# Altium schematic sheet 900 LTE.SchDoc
size Letter; Organization: Toradex Solutions Inc.; Address1: 6415 Northwest Drive; Address2: Mississauga, ON, L4V 1X1; Address3: Canada
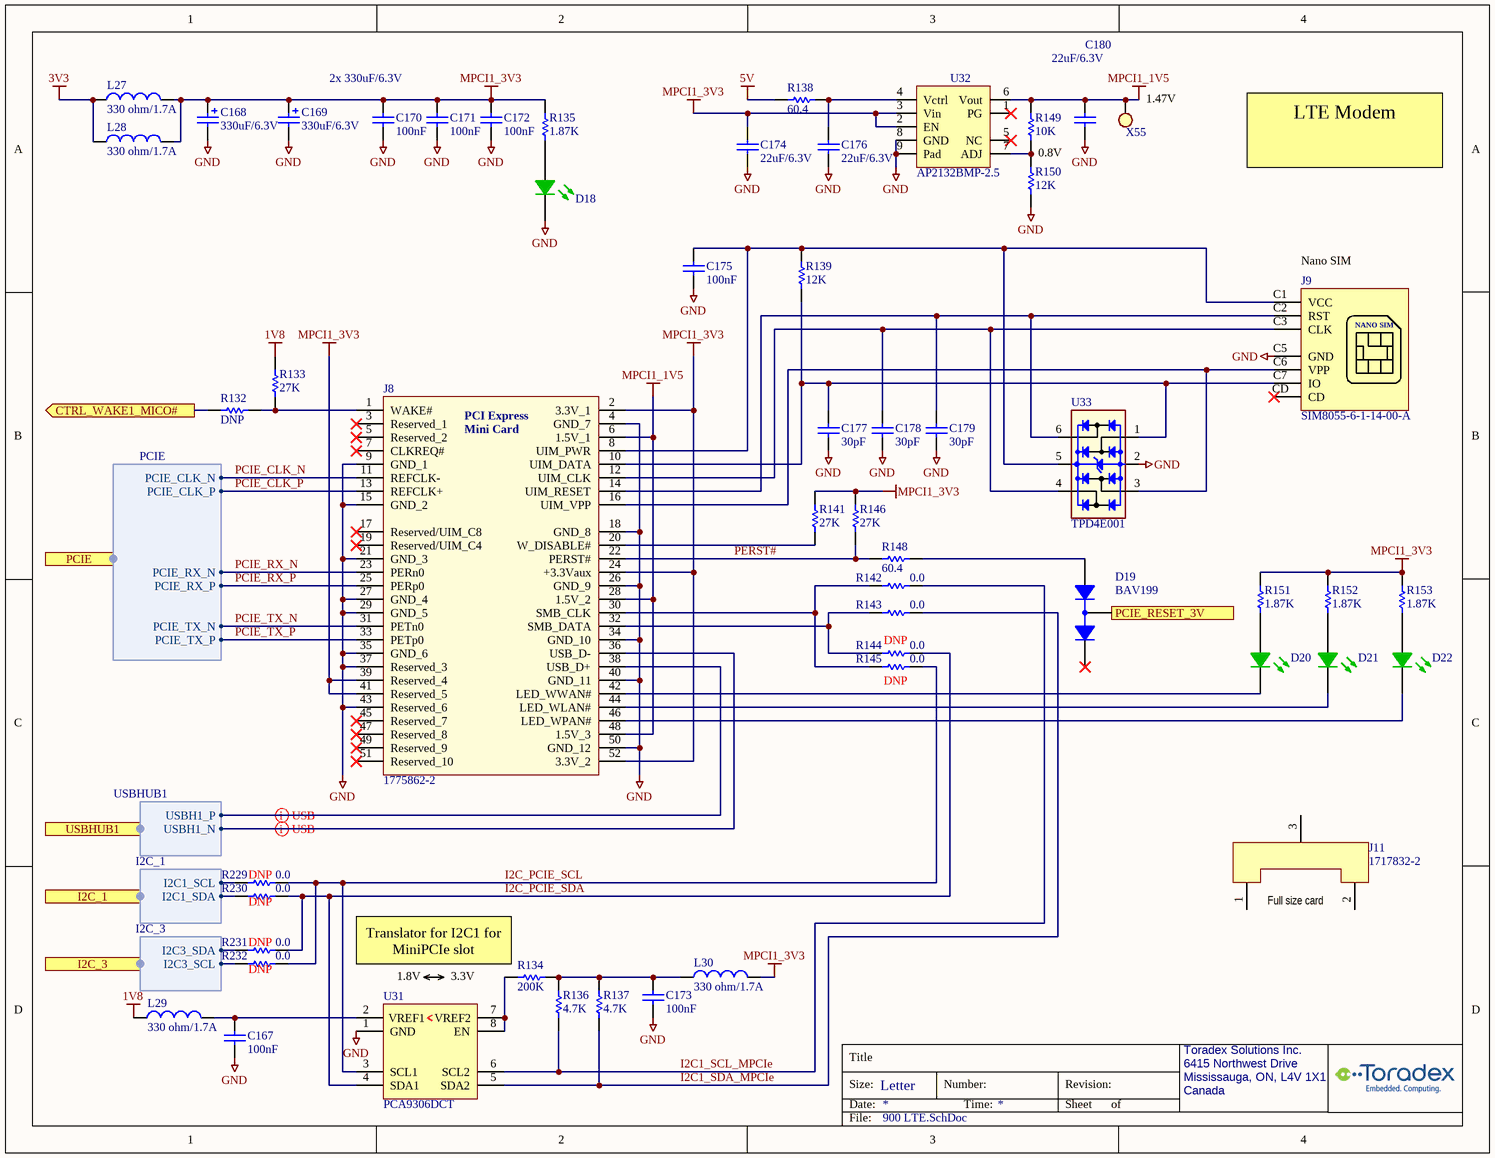
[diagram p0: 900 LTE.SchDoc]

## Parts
C167  100nF  [C0402_CAPC1005L]
C168  330uF/6.3V  [CAN-SMD-D630]
C169  330uF/6.3V  [CAN-SMD-D630]
C170  100nF  [C0402_CAPC1005L]
C171  100nF  [C0402_CAPC1005L]
C172  100nF  [C0402_CAPC1005L]
C173  100nF  [C0402_CAPC1005L]
C174  22uF/6.3V  [C0402_CAPC1005L]
C175  100nF  [C0402_CAPC1005L]
C176  22uF/6.3V  [C0402_CAPC1005L]
C177  value 30pF  [C/0603]  (hidden comment: 0958-Cap-0603-30pF/50V)
C178  value 30pF  [C/0603]  (hidden comment: 0958-Cap-0603-30pF/50V)
C179  value 30pF  [C/0603]  (hidden comment: 0958-Cap-0603-30pF/50V)
C180  22uF/6.3V  [C0402_CAPC1005L]
D18  Status  [LED-SMT-0603_APT1608CGCK]  (value not drawn)
D19  BAV199  [SOT23_M]
D20  Status  [LED-SMT-0603_APT1608CGCK]  (value not drawn)
D21  Status  [LED-SMT-0603_APT1608CGCK]  (value not drawn)
D22  Status  [LED-SMT-0603_APT1608CGCK]  (value not drawn)
J8  1775862-2  [17758622_FULL_SIZE]
J9  SIM8055-6-1-14-00-A  [SIM8055611400A]
J11  1717832-2  [MINI_PCIE_52PIN_CARD_LATCH_ALT]
L27  value 330 ohm/1.7A  [INDC1608x095]  (hidden comment: 0405-Fer-0603-330ohm/1.7A)
L28  value 330 ohm/1.7A  [INDC1608x095]  (hidden comment: 0405-Fer-0603-330ohm/1.7A)
L29  value 330 ohm/1.7A  [INDC1608x095]  (hidden comment: 0405-Fer-0603-330ohm/1.7A)
L30  value 330 ohm/1.7A  [INDC1608x095]  (hidden comment: 0405-Fer-0603-330ohm/1.7A)
R132  value DNP  [R/0603]  (hidden comment: 0000-Res-0603-DNP)
R133  value 27K  [R0402_RESC1005L]  (hidden comment: 1538-Res-0402-27k)
R134  value 200K  [R/0603]  (hidden comment: 1367-Res-0603-200K)
R135  value 1.87K  [R0402_RESC1005L]  (hidden comment: 1536-Res-0402-1.87K)
R136  value 4.7K  [R0402_RESC1005L]  (hidden comment: 2233-Res-0402-4.7K)
R137  value 4.7K  [R0402_RESC1005L]  (hidden comment: 2233-Res-0402-4.7K)
R138  value 60.4  [R/0603]  (hidden comment: 2199-Res-0603-60.4)
R139  value 12K  [R0402_RESC1005L]  (hidden comment: 1537-Res-0402-12K)
R141  value 27K  [R0402_RESC1005L]  (hidden comment: 1538-Res-0402-27k)
R142  value 0.0  [R/0603]  (hidden comment: 0195-Res-0603-0.0ohm)
R143  value 0.0  [R/0603]  (hidden comment: 0195-Res-0603-0.0ohm)
R144  value 0.0  [R/0603]  (hidden comment: 0195-Res-0603-0.0ohm)  (no BOM)
R145  value 0.0  [R/0603]  (hidden comment: 0195-Res-0603-0.0ohm)  (no BOM)
R146  value 27K  [R0402_RESC1005L]  (hidden comment: 1538-Res-0402-27k)
R148  value 60.4  [R/0603]  (hidden comment: 2199-Res-0603-60.4)
R149  value 10K  [R0402_RESC1005L]  (hidden comment: 1572-Res-0402-10K)
R150  value 12K  [R0402_RESC1005L]  (hidden comment: 1537-Res-0402-12K)
R151  value 1.87K  [R0402_RESC1005L]  (hidden comment: 1536-Res-0402-1.87K)
R152  value 1.87K  [R0402_RESC1005L]  (hidden comment: 1536-Res-0402-1.87K)
R153  value 1.87K  [R0402_RESC1005L]  (hidden comment: 1536-Res-0402-1.87K)
R229  value 0.0  [R/0603]  (hidden comment: 0195-Res-0603-0.0ohm)  (no BOM)
R230  value 0.0  [R/0603]  (hidden comment: 0195-Res-0603-0.0ohm)  (no BOM)
R231  value 0.0  [R/0603]  (hidden comment: 0195-Res-0603-0.0ohm)  (no BOM)
R232  value 0.0  [R/0603]  (hidden comment: 0195-Res-0603-0.0ohm)  (no BOM)
U31  PCA9306DCT  [TSSO3x5-G8/X.35]
U32  AP2132BMP-2.5  [SOP-9 TP_ALT]
U33  TPD4E001  [SOT23-6]
X55  000-TestPoint2  [TestPoint_3]  (value not drawn)

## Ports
CTRL_WAKE1_MICO# (out), I2C_1 (harness I2C_1), I2C_3 (harness I2C_3), PCIE (harness PCIe), PCIE_RESET_3V (in), USBHUB1 (harness USBHUB1)

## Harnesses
PCIE: PCIE_CLK_N, PCIE_CLK_P, PCIE_RX_N, PCIE_RX_P, PCIE_TX_N, PCIE_TX_P
USBHUB1: USBH1_N, USBH1_P
I2C_1: I2C1_SDA, I2C1_SCL
I2C_3: I2C3_SDA, I2C3_SCL

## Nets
1V8: L29.1 R133.1
3V3: L27.1 L28.1
5V: R138.2
GND: C167.1 C168.2 C169.2 C170.1 C171.1 C172.1 C173.1 C174.1 C175.1 C176.1 C177.1 C178.1 C179.1 C180.1 D18.2(K) J8.4(GND_7) J8.9(GND_1) J8.15(GND_2) J8.18(GND_8) J8.21(GND_3) J8.26(GND_9) J8.27(GND_4) J8.29(GND_5) J8.34(GND_10) J8.35(GND_6) J8.37(Reserved_3) J8.40(GND_11) J8.43(Reserved_6) J8.50(GND_12) J9.C5(GND) R150.1 U31.1(GND) U32.8(GND) U32.9(Pad) U33.2
MPCI1_1V5: C180.2 J8.6(1.5V_1) J8.28(1.5V_2) J8.48(1.5V_3) R149.2 U32.6(Vout) X55.1
MPCI1_3V3: C168.1 C169.1 C170.2 C171.2 C172.2 C174.2 J8.2(3.3V_1) J8.24(+3.3Vaux) J8.39(Reserved_4) J8.41(Reserved_5) J8.52(3.3V_2) L27.2 L28.2 L30.2 R135.2 R141.1 R146.1 R151.2 R152.2 R153.2 U32.2(EN) U32.3(Vin)
CTRL_WAKE1_MICO#: R132.1 ; port CTRL_WAKE1_MICO#
I2C1_SCL_MPCIe: R136.1 R142.1 U31.6(SCL2)
I2C1_SDA_MPCIe: R137.1 R143.1 U31.5(SDA2)
I2C_PCIE_SCL: R145.1 R229.1 R232.1 U31.3(SCL1)
I2C_PCIE_SDA: R144.1 R230.1 R231.1 U31.4(SDA1)
PCIE_CLK_N: J8.11(REFCLK-) ; port PCIE.PCIE_CLK_N
PCIE_CLK_P: J8.13(REFCLK+) ; port PCIE.PCIE_CLK_P
PCIE_RESET_3V: D19.3(K1/A2) ; port PCIE_RESET_3V
PCIE_RX_N: J8.23(PERn0) ; port PCIE.PCIE_RX_N
PCIE_RX_P: J8.25(PERp0) ; port PCIE.PCIE_RX_P
PCIE_TX_N: J8.31(PETn0) ; port PCIE.PCIE_TX_N
PCIE_TX_P: J8.33(PETp0) ; port PCIE.PCIE_TX_P
PERST#: J8.22(PERST#) R146.2 R148.2
NetC167_2: C167.2 L29.2 U31.2(VREF1)
NetC173_2: C173.2 L30.1 R134.1 R136.2 R137.2
NetC175_2: C175.2 J8.8(UIM_PWR) J9.C1(VCC) R139.2 U33.5
NetC176_2: C176.2 R138.1 U32.4(Vctrl)
NetC177_2: C177.2 J8.10(UIM_DATA) J9.C7(IO) R139.1 U33.1
NetC178_2: C178.2 J8.12(UIM_CLK) J9.C3(CLK) U33.4
NetC179_2: C179.2 J8.14(UIM_RESET) J9.C2(RST) U33.6
NetD18_1: D18.1(A) R135.1
NetD19_1: D19.1(A1) R148.1
NetD20_1: D20.1(A) R151.1
NetD20_2: D20.2(K) J8.42(LED_WWAN#)
NetD21_1: D21.1(A) R152.1
NetD21_2: D21.2(K) J8.44(LED_WLAN#)
NetD22_1: D22.1(A) R153.1
NetD22_2: D22.2(K) J8.46(LED_WPAN#)
NetJ8_1: J8.1(WAKE#) R132.2 R133.2
NetJ8_16: J8.16(UIM_VPP) J9.C6(VPP) U33.3
NetJ8_20: J8.20(W_DISABLE#) R141.2
NetJ8_30: J8.30(SMB_CLK) R142.2 R145.2
NetJ8_32: J8.32(SMB_DATA) R143.2 R144.2
NetJ8_36: J8.36(USB_D-) ; port USBHUB1.USBH1_N
NetJ8_38: J8.38(USB_D+) ; port USBHUB1.USBH1_P
NetR134_2: R134.2 U31.7(VREF2) U31.8(EN)
NetR149_1: R149.1 R150.2 U32.7(ADJ)
NetR229_2: R229.2 ; port I2C_1.I2C1_SCL
NetR230_2: R230.2 ; port I2C_1.I2C1_SDA
NetR231_2: R231.2 ; port I2C_3.I2C3_SDA
NetR232_2: R232.2 ; port I2C_3.I2C3_SCL

Not connected (* = marked no-connect by the designer): D19 2(K2)*; J8 3(Reserved_1)* 5(Reserved_2)* 7(CLKREQ#)* 17(Reserved/UIM_C8)* 19(Reserved/UIM_C4)* 45(Reserved_7)* 47(Reserved_8)* 49(Reserved_9)* 51(Reserved_10)*; J9 CD*; J11 1 2 3; U32 1(PG)* 5(NC)*

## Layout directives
differential pair; differential pair class USBH1; differential pair class USB: NetJ8_36, NetJ8_38

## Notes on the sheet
- 2x 330uF/6.3V
- (near X55) 1.47V
- 0.8V
- LTE Modem
- (near J9) Nano SIM
- (near R144) DNP
- (near R145) DNP
- (near R229) DNP
- (near R230) DNP
- (near J11) Full size card
- (near R231) DNP
- (near R232) DNP
- (near R134) Translator for I2C1 for MiniPCIe slot
- (near U31) 1.8V
- 3.3V

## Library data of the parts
C167 C170-C173 C175 = 1566-Cap-0402-100nF/50V: (-55 to 125 DegC AEC) Cap Ceramic 0.1uF 50V X7R 10% 0402; MfrNo: GRT155R71H104KE01D; Mfr: Murata; Alt: CL05B104KB54PNC,GCM155R71H104ME02D,GCM155R71H104KE02D,GCM155R71H104KE02J; PN: 1566
C168 C169 = 2241-Cap-6.6x6.6-330uF/6.3V: (-55 to 105 DegC) CAP ALUM POLY 33UF 6.3V 20% SMD 10mohm 6.6x6.6x6.1mm Ir:3.9A (100kHz); Mfr: United Chemi-Con; MfrNo: APXF6R3ARA331MF61G; PN: 2241
C174 C176 C180 = 2404-Cap-0402-22uF/6.3V: (-55 to 85 DegC) CAP CER 22UF 6.3V 20% X5R 0402; MfrNo: GRM155R60J226ME11D; Mfr: Murata; PN: 2404
C177-C179 = 0958-Cap-0603-30pF/50V: (-55 - 125 DegC) CAP CER 30PF 50V C0G/NP0 0603; Mfr: Kyocera AVX; MfrNo: 06035A300JAT2A\4K; PN: 958; Alt: CC0603GRNPO9BN300,06031A300J4T2A
D18 D20-D22 = 0333-LED Green 0603: (-40 to 85 DegC) LED GREEN 0603 50mcd; MfrNo: APT1608CGCK; Mfr: Kingbright; Alt: 754-1357-1-ND; Alt2: 160-1834-1-ND; PN: 333; DR: 754-1116-6-ND; DR2: 604-APT1608CGCK
D19 = 0859-BAV199: (-65 to 150 DegC) DIODE ARRAY SeriesConnection 85V 140MA SOT23-3 Low Leakage Ilk=5nA; MfrNo: BAV199-7-F; Mfr: Diodes Incorporated; Alt: BAV199E6433HTMA1,BAV199HMT116,BAV199,235; PN: 859
J8 = 1390-Conn-MiniPCIe: (-55 to 85 DegC) CONN MINI EXPRESS CARD 52POS SMD; Mfr: TE Connectivity; PN: 1390
J9 = 1401-Conn-NanoSIM: (-40 to 85 DegC) CONN SIM NANO PUSH PULL 6P, 1.35mm height; Mfr: Global Connector Technology; PN: 1401
J11 = 1391-Conn-MiniPCIe-Latch: (-55 to 85 DegC) CONN MINI EXPRESS CARD LATCH SMD; Mfr: TE Connectivity; PN: 1391; Note: Latch for PN 25001390
L27-L30 = 0405-Fer-0603-330ohm/1.7A: (-55 to 125 DegC) FERRITE BEAD 330 OHM 0603 1.7A 80mohm, typ 48mohm; Mfr: TDK Corporation; MfrNo: MPZ1608S331ATA00; PN: 405; TR: 445-5221-2-ND; DR: 445-5221-6-ND; DR2: 810-MPZ1608S331ATA00
R132 = 0000-Res-0603-DNP: RES 0603
R133 R141 R146 = 1538-Res-0402-27k: (-55 to 155 DegC AEC) RES 27K OHM 1% 1/16W 100ppm 0402; Mfr: Stackpole Electronics; MfrNo: RMCF0402FT27K0; PN: 1538; Alt: AC0402FR-0727KL,CRGCQ0402F27K
R134 = 1367-Res-0603-200K: (-55 to 155 DegC) RES SMD 200K 1% 1/10W 0603 100ppm; Mfr: Stackpole Electronics; MfrNo: RMCF0603FT200K; Alt: CR0603-FX-2003ELF,RC0603FR-07200KL,RK73H1JTTD2003F; PN: 1367
R135 R151-R153 = 1536-Res-0402-1.87K: (-55 to 155 DegC AEC) RES 1.87K OHM 1% 1/16W 100ppm 0402; MfrNo: RMCF0402FT1K87; Mfr: Stackpole Electronics; Alt: AC0402FR-071K87L,RK73H1ETTP1871F,ERJ-2RKF1871X; PN: 1536
R136 R137 = 2233-Res-0402-4.7K: (-55 to 155 DegC) RES 4.70K OHM 1/16W 1% 0402 100ppm; MfrNo: RC0402FR-074K7L; Mfr: Yageo; PN: 2233
R138 R148 = 2199-Res-0603-60.4: (-55 to 155 DegC) RES SMD 60.4 OHM 1% 1/10W 0603; MfrNo: CR0603-FX-60R4ELF; Mfr: Bourns; PN: 2199; Desc: (-55 to 155 DegC) RES SMD 60.4k OHM 1% 1/10W 0603
R139 R150 = 1537-Res-0402-12K: (-55 to 155 DegC AEC) RES 12K OHM 1% 1/16W 100ppm 0402; Mfr: Stackpole Electronics; MfrNo: RMCF0402FT12K0; PN: 1537; Alt: AC0402FR-0712KL,CRGCQ0402F12K
R142-R145 R229-R232 = 0195-Res-0603-0.0ohm: RES 0.0 OHM 1/10W JUMP 0603; Mfr: Samsung; MfrNo: RC1608J000CS; Alt: 311-0.0GRCT-ND; Alt2: A106051CT-ND; PN: 195; TR: 1276-3510-2-ND
R149 = 1572-Res-0402-10K: (-55 to 155 DegC AEC) RES 10K OHM 1% 1/16W 100ppm 0402; Mfr: Stackpole Electronics; MfrNo: RMCF0402FT10K0; PN: 1572; Alt: AC0402FR-0710KL,AC0402FR-1310KL,CRGCQ0402F10K
U31 = 0972-PCA9306DCT: (-40 to 85 DegC) IC TRANSLTR BIDIRECTIONAL I2C SM8; MfrNo: PCA9306DCTR; Mfr: Texas Instruments; PN: 972
U32 = 1467-AP2132BMP-2.5: (-40 to 85 DegC) IC REG LDO LINEAR POS ADJ 5V 2A 8SO; MfrNo: AP2132BMP-2.5TRG1; Mfr: Diodes; PN: 1467; Desc: (-40 to 85 DegC) IC REG BUCK ADJ Sync 5A Vin:3.8 to 40V 100-2200kHz FSS (spread spectrum) MaxDuty:100% SO-8EP; Note: These can be also used with adjust Voltage circuit: AP2132BMP-1.2TRG1, AP2132BMP-1.5TRG1
U33 = 0740-TPD4E001: (-40 to 125 DegC AEC) TVS DIODE 5.5VWM 16VC SOT-23-6; MfrNo: TPD4E001QDBVRQ1; Mfr: Texas Instruments; PN: 740; Alt: TPD4E001DBVR
X55 = 000-TestPoint2: TestPoint SMD; Note: PCB footprint only, no parts to buy or assemble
